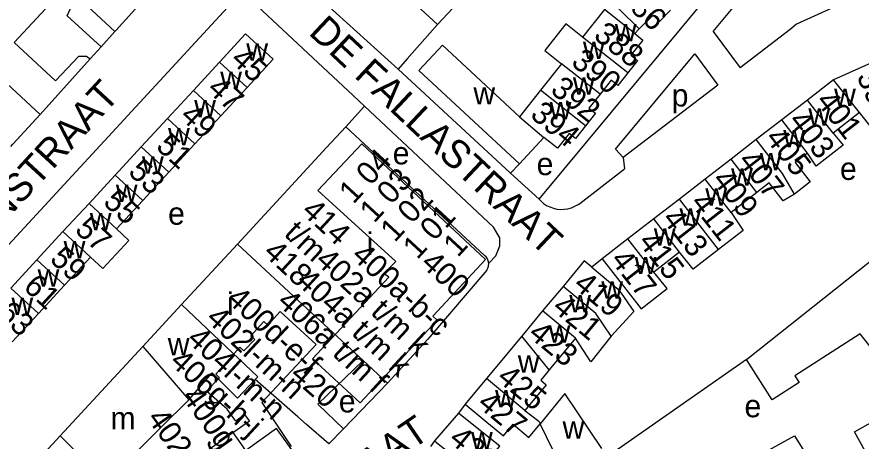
# Model space of a CAD drawing. Extents: x 159045 to 160918, y 380454 to 382516.
# Drawn here: x 159786.4 to 159936.2, y 381507.9 to 381583.2 of the extents above; entities that cross this region are included whole.
import ezdxf

# ---------------------------------------------------------------- set-up
doc = ezdxf.new("R2010")
doc.units = 0
for name, color, linetype in [('BLT_Basislijn', 7, 'Continuous'), ('BLT_Bebouwing', 7, 'Continuous'), ('BLT_Centroide', 7, 'Continuous'), ('BLT_Huisnummer', 7, 'Continuous'), ('BLT_Huisnummer_ tussenligend', 7, 'Continuous'), ('BLT_Huisnummer_reeks', 7, 'Continuous'), ('BLT_Huisnummer_zonder_bebouwing', 7, 'Continuous'), ('BLT_Onderverdeling_panden', 7, 'Continuous'), ('BLT_Plantopo', 7, 'Continuous'), ('BLT_Straatnaam', 7, 'Continuous')]:
    doc.layers.add(name, color=color, linetype=linetype)

msp = doc.modelspace()

# ---------------------------------------------------------------- linework, layer by layer
at = {"layer": 'BLT_Basislijn'}
for p, q in [((159904.79, 381629.03), (159861.07, 381581.84)), ((159879.08, 381550.82), (159931.69, 381614.23)), ((159909.99, 381580.6), (159934.12, 381609.7)), ((159803.8, 381580.61), (159778.83, 381603.82)), ((159848.38, 381593.58), (159861.07, 381581.84)), ((159765.35, 381589.16), (159790.52, 381565.9)), ((159804.04, 381580.87), (159803.8, 381580.61)), ((159896.07, 381580.24), (159896.87, 381581.07)), ((159803.8, 381580.61), (159801.33, 381577.88)), ((159909.99, 381580.6), (159914.75, 381574.14)), ((159801.33, 381577.88), (159799.41, 381575.74)), ((159906.7, 381576.64), (159910.79, 381571.1)), ((159799.41, 381575.74), (159790.52, 381565.9)), ((159874.02, 381555.44), (159854.07, 381573.92)), ((159910.79, 381571.1), (159894.03, 381558.25)), ((159848.08, 381567.38), (159844.75, 381563.69)), ((159894.03, 381558.25), (159894.27, 381556.2)), ((159874.02, 381555.44), (159875.58, 381557.1)), ((159879.08, 381550.82), (159874.02, 381555.44)), ((159886.29, 381550.1), (159894.27, 381556.2)), ((159879.87, 381550.1), (159879.08, 381550.82)), ((159890.29, 381540.22), (159888.45, 381538.75)), ((159915.87, 381522.39), (159891.17, 381505.09)), ((159844.35, 381510.07), (159852.18, 381518.17)), ((159865.97, 381514.42), (159864.79, 381512.84)), ((159794.09, 381508.82), (159785.95, 381500.02)), ((159860.52, 381507.91), (159859.82, 381506.88))]:
    msp.add_line(p, q, dxfattribs=at)
for points in [[(159839.03, 381602.45), (159835.58, 381598.61), (159834.37, 381596.71), (159834.17, 381595.42), (159834.51, 381592.37), (159839.38, 381587.26), (159854.07, 381573.92)], [(159812.23, 381595.28), (159814.81, 381592.83), (159804.04, 381580.87)], [(159941.77, 381589.71), (159924.75, 381581.94), (159923.64, 381580.95), (159914.75, 381574.14)], [(159801.33, 381577.88), (159795.33, 381583.42), (159796.15, 381585.26), (159793.91, 381587.33), (159785.89, 381578.65), (159793.25, 381571.84), (159797.38, 381576.25), (159798.77, 381576.27), (159799.41, 381575.74)], [(159848.08, 381567.38), (159846.1, 381569.24), (159828.23, 381585.97), (159825.45, 381586.12), (159823.76, 381584.89), (159762.94, 381518.98), (159762.66, 381518.45)], [(159861.07, 381581.84), (159859.71, 381580.34), (159855.66, 381575.77), (159854.07, 381573.92)], [(159894.03, 381558.25), (159892.67, 381559.73), (159906.7, 381576.64)], [(159870.14, 381539.48), (159871.41, 381540.76), (159872.09, 381542.53), (159872.09, 381543.96), (159871, 381545.87), (159848.08, 381567.38)], [(159785.32, 381560.2), (159785.67, 381560.59), (159790.52, 381565.9)], [(159879.87, 381550.1), (159880.42, 381549.74), (159881, 381549.45), (159881.62, 381549.23), (159882.26, 381549.09), (159882.91, 381549.03), (159883.56, 381549.05), (159884.21, 381549.15), (159884.84, 381549.32), (159885.44, 381549.58), (159886.01, 381549.9), (159886.29, 381550.1)]]:
    msp.add_lwpolyline(points, dxfattribs=at)
at = {"layer": 'BLT_Bebouwing'}
for p, q in [((159896.07, 381580.24), (159897.5, 381579.11)), ((159817.73, 381570.16), (159822.37, 381575.17)), ((159883.07, 381574.89), (159879.33, 381570.18)), ((159939.15, 381575.53), (159931.35, 381572.05)), ((159827.24, 381570.68), (159822.61, 381565.66)), ((159813.1, 381565.14), (159817.73, 381570.16)), ((159879.33, 381570.18), (159875.6, 381565.47)), ((159926.7, 381568.44), (159922.16, 381564.93)), ((159935.97, 381566.21), (159931.26, 381562.56)), ((159808.46, 381560.13), (159813.1, 381565.14)), ((159822.61, 381565.66), (159817.98, 381560.64)), ((159922.16, 381564.93), (159917.63, 381561.41)), ((159844.75, 381563.69), (159869.4, 381540.86)), ((159879.95, 381561.8), (159875.58, 381557.1)), ((159882.33, 381559.91), (159879.95, 381561.8)), ((159917.63, 381561.41), (159913.16, 381557.95)), ((159803.83, 381555.11), (159808.46, 381560.13)), ((159817.98, 381560.64), (159813.35, 381555.62)), ((159913.16, 381557.95), (159908.59, 381554.41)), ((159813.35, 381555.62), (159808.72, 381550.6)), ((159799.2, 381550.1), (159803.83, 381555.11)), ((159908.59, 381554.41), (159904.01, 381550.86)), ((159904.01, 381550.86), (159899.44, 381547.32)), ((159917.74, 381552.05), (159913.17, 381548.5)), ((159794.56, 381545.08), (159799.2, 381550.1)), ((159808.72, 381550.6), (159804.09, 381545.58)), ((159899.44, 381547.32), (159894.86, 381543.77)), ((159789.93, 381540.07), (159794.56, 381545.08)), ((159894.86, 381543.77), (159890.29, 381540.22)), ((159825.53, 381542.87), (159815.62, 381532.14)), ((159799.46, 381540.56), (159794.83, 381535.55)), ((159904.03, 381541.4), (159899.46, 381537.85)), ((159915.87, 381522.39), (159940.17, 381541.66)), ((159785.29, 381535.05), (159789.93, 381540.07)), ((159794.83, 381535.55), (159790.2, 381530.53)), ((159883.34, 381535.35), (159879.71, 381530.98)), ((159815.62, 381532.14), (159808.75, 381524.7)), ((159790.2, 381530.53), (159785.57, 381525.51)), ((159879.71, 381530.98), (159876.01, 381526.51)), ((159876.01, 381526.51), (159869.75, 381518.97)), ((159885.54, 381526.14), (159880.87, 381520.5)), ((159808.75, 381524.7), (159804.29, 381519.88)), ((159847.84, 381522.19), (159839.82, 381514.42)), ((159852.18, 381518.17), (159847.84, 381522.19)), ((159804.29, 381519.88), (159794.09, 381508.82)), ((159816.89, 381515.22), (159821.04, 381519.99)), ((159836.25, 381512.18), (159828.69, 381518.81)), ((159869.75, 381518.97), (159865.97, 381514.42)), ((159880.32, 381517.89), (159876.55, 381513.33)), ((159883.66, 381516.34), (159879.27, 381510.91)), ((159890.2, 381506.54), (159883.66, 381516.34)), ((159844.35, 381510.07), (159839.82, 381514.42)), ((159864.79, 381512.84), (159860.52, 381507.91)), ((159841.74, 381507.36), (159844.35, 381510.07))]:
    msp.add_line(p, q, dxfattribs=at)
for points in [[(159895.05, 381591.65), (159890.66, 381587.17), (159893.31, 381584.57), (159896.87, 381581.07)], [(159896.07, 381580.24), (159893.58, 381582.21), (159890.68, 381584.51), (159886.8, 381579.6)], [(159902.43, 381584.4), (159900.47, 381582.41), (159899.31, 381583.55), (159896.87, 381581.07)], [(159886.8, 381579.6), (159883.82, 381581.96), (159880.09, 381577.25), (159883.07, 381574.89)], [(159822.37, 381575.17), (159826.99, 381580.18), (159831.86, 381575.69), (159827.24, 381570.68)], [(159875.58, 381557.1), (159857.74, 381573.7), (159861.15, 381577.36), (159861.92, 381578.19), (159875.6, 381565.47)], [(159897.5, 381579.11), (159895.38, 381576.43), (159896.57, 381575.49), (159894.81, 381573.26)], [(159894.81, 381573.26), (159893.05, 381571.04), (159891.88, 381571.96), (159889.91, 381569.48)], [(159931.35, 381572.05), (159926.7, 381568.44)], [(159889.91, 381569.48), (159887.94, 381566.99), (159889.08, 381566.09), (159887.32, 381563.86)], [(159944.02, 381565.92), (159938.24, 381563.33), (159935.97, 381566.21)], [(159844.75, 381563.69), (159841.36, 381560.01), (159825.53, 381542.87)], [(159887.32, 381563.86), (159885.55, 381561.62), (159884.4, 381562.53), (159882.33, 381559.91)], [(159931.26, 381562.56), (159933.07, 381560.44), (159928.25, 381556.69), (159926.73, 381559.04)], [(159926.73, 381559.04), (159924.54, 381557.34), (159927.22, 381553.89), (159924.41, 381551.7)], [(159924.41, 381551.7), (159922.4, 381550.55), (159919.91, 381553.74), (159917.74, 381552.05)], [(159913.17, 381548.5), (159915.28, 381545.27), (159910.94, 381541.9)], [(159804.09, 381545.58), (159806.28, 381543.52), (159801.66, 381538.51), (159799.46, 381540.56)], [(159910.94, 381541.9), (159906.43, 381538.39), (159904.03, 381541.4)], [(159870.14, 381539.48), (159870.07, 381539.87), (159869.91, 381540.24), (159869.69, 381540.58), (159869.4, 381540.86)], [(159890.29, 381540.22), (159897.18, 381531.35), (159901.83, 381534.96), (159899.46, 381537.85)], [(159869.83, 381538.21), (159870.01, 381538.57), (159870.12, 381538.95), (159870.14, 381539.48)], [(159888.45, 381538.75), (159887.09, 381539.87), (159883.34, 381535.35)], [(159888.45, 381538.75), (159892.91, 381535.05), (159893.63, 381534.13), (159895.89, 381530.86), (159891.89, 381526.49)], [(159869.83, 381538.21), (159859.32, 381526), (159852.18, 381518.17)], [(159937.83, 381524.66), (159936.09, 381526.91), (159924.45, 381519.49), (159925.24, 381518.25), (159920.47, 381515.21), (159915.87, 381522.39)], [(159891.89, 381526.49), (159888.27, 381521.93), (159885.54, 381526.14)], [(159828.69, 381518.81), (159825.53, 381515.52), (159821.04, 381519.99)], [(159880.87, 381520.5), (159879.37, 381518.68), (159880.32, 381517.89)], [(159811.92, 381510.27), (159816.89, 381515.22)], [(159865.97, 381514.42), (159869.82, 381511.23), (159872.77, 381508.78), (159874.51, 381510.88), (159877.28, 381508.51), (159879.27, 381510.91)], [(159876.55, 381513.33), (159879.03, 381511.39), (159879.27, 381510.91)], [(159841.74, 381507.36), (159837.78, 381510.83), (159836.25, 381512.18)], [(159860.52, 381507.91), (159864.42, 381504.78), (159867.11, 381502.62), (159866.97, 381502.45), (159869.86, 381500), (159871.91, 381502.3), (159869.71, 381504.2), (159872.09, 381506.95), (159868.68, 381509.7), (159864.79, 381512.84)], [(159794.09, 381508.82), (159802.26, 381500.66), (159811.92, 381510.28)], [(159884.22, 381501.89), (159882.63, 381503.99), (159879.27, 381510.91)], [(159937.71, 381497.42), (159933.89, 381504.38), (159936.95, 381506.06), (159935.05, 381509.52), (159938.45, 381511.39)], [(159837.07, 381503.66), (159834.17, 381507.73), (159832.5, 381510.08), (159827.04, 381506.2), (159824.65, 381509.57), (159822.2, 381507.82)], [(159919.94, 381506.34), (159924.4, 381508.81), (159928.52, 381502.22), (159928.69, 381502.27), (159929.95, 381500), (159932.38, 381495.64)]]:
    msp.add_lwpolyline(points, dxfattribs=at)
at = {"layer": 'BLT_Onderverdeling_panden'}
for p, q in [((159894.81, 381573.26), (159886.8, 381579.6)), ((159827.24, 381570.68), (159822.37, 381575.17)), ((159889.91, 381569.48), (159883.07, 381574.89)), ((159935.97, 381566.21), (159931.35, 381572.05)), ((159822.61, 381565.66), (159817.73, 381570.16)), ((159887.32, 381563.86), (159879.33, 381570.18)), ((159931.26, 381562.56), (159926.7, 381568.44)), ((159817.98, 381560.64), (159813.1, 381565.14)), ((159875.6, 381565.47), (159879.95, 381561.8)), ((159926.73, 381559.04), (159922.16, 381564.93)), ((159813.35, 381555.62), (159808.46, 381560.13)), ((159917.74, 381552.05), (159913.16, 381557.95)), ((159808.72, 381550.6), (159803.83, 381555.11)), ((159913.17, 381548.5), (159908.59, 381554.41)), ((159910.94, 381541.9), (159904.01, 381550.86)), ((159804.09, 381545.58), (159799.2, 381550.1)), ((159904.03, 381541.4), (159899.44, 381547.32)), ((159799.46, 381540.56), (159794.56, 381545.08)), ((159899.46, 381537.85), (159894.86, 381543.77)), ((159836.34, 381532.85), (159825.53, 381542.87)), ((159794.83, 381535.55), (159789.93, 381540.07)), ((159790.2, 381530.53), (159785.29, 381535.05)), ((159847.84, 381522.19), (159836.34, 381532.85)), ((159885.54, 381526.14), (159879.71, 381530.98)), ((159880.87, 381520.5), (159876.01, 381526.51)), ((159808.75, 381524.7), (159816.89, 381515.22)), ((159876.55, 381513.33), (159869.75, 381518.97))]:
    msp.add_line(p, q, dxfattribs=at)
for points in [[(159924.41, 381551.7), (159922.3, 381555.39), (159917.63, 381561.41)], [(159891.89, 381526.49), (159889.16, 381530.52), (159883.34, 381535.35)], [(159815.62, 381532.14), (159829.16, 381519.29), (159828.69, 381518.81)]]:
    msp.add_lwpolyline(points, dxfattribs=at)
at = {"layer": 'BLT_Plantopo'}
msp.add_lwpolyline([(159839.82, 381552.36), (159847.61, 381560.66), (159869.59, 381540.15), (159860.21, 381530.07), (159860.98, 381529.35), (159847.32, 381514.65), (159838.89, 381522.49), (159852.39, 381536.99), (159851.55, 381537.64), (159853.64, 381539.78)], close=True, dxfattribs=at)
msp.add_lwpolyline([(159811.61, 381500.16), (159827.68, 381511.47), (159826.88, 381512.58), (159825.24, 381511.41), (159823.73, 381513.52), (159820.04, 381516.72), (159822.36, 381519.1), (159821.7, 381519.73), (159825.99, 381524.55), (159826.66, 381523.93), (159828.6, 381525.91), (159827.89, 381526.59), (159830.25, 381529.09), (159830.94, 381528.46), (159833.12, 381530.89), (159839.53, 381525.01), (159829.89, 381514.71), (159835.06, 381506.91)], dxfattribs=at)

# ---------------------------------------------------------------- texts
at = {"layer": 'BLT_Centroide'}
for s, p in [('w', (159892.52, 381578.88)), ('w', (159827.11, 381575.42)), ('w', (159886.87, 381575.72)), ('w', (159822.48, 381570.42)), ('w', (159885.09, 381569.38)), ('w', (159867.42, 381567.66)), ('p', (159902.62, 381567.3)), ('w', (159931.45, 381567.41)), ('w', (159817.86, 381565.39)), ('w', (159880.96, 381565.03)), ('w', (159926.89, 381563.88)), ('w', (159813.22, 381560.39)), ('w', (159922.42, 381560.03)), ('e', (159853.1, 381557.02)), ('w', (159808.59, 381555.36)), ('e', (159878.65, 381555.11)), ('w', (159918.27, 381555.97)), ('e', (159932.49, 381554.26)), ('w', (159913.17, 381553.22)), ('w', (159803.95, 381550.36)), ('w', (159908.59, 381549.69)), ('e', (159813.23, 381546.3)), ('w', (159799.33, 381545.33)), ('w', (159904.02, 381546.12)), ('i', (159848.48, 381540.94)), ('w', (159899.45, 381542.59)), ('w', (159794.69, 381540.31)), ('w', (159896.06, 381537.52)), ('w', (159790.06, 381535.3)), ('w', (159890.12, 381533.19)), ('i', (159823.69, 381530.27)), ('w', (159785.42, 381530.28)), ('w', (159884.44, 381530.75)), ('w', (159880.78, 381525.36)), ('w', (159813.17, 381523.09)), ('w', (159875.31, 381520.02)), ('w', (159871.26, 381513.88)), ('e', (159843.53, 381512.96)), ('e', (159915.54, 381512.1)), ('m', (159803, 381509.94)), ('w', (159883.25, 381508.28)), ('w', (159867, 381506.41))]:
    msp.add_text(s, height=4, dxfattribs=at).set_placement(p)
at = {"layer": 'BLT_Huisnummer'}
for s, rotation, p in [('388', 321.6345, (159888.56, 381579.55)), ('45', 317.3116, (159824.13, 381575.36)), ('399', 294.083, (159935.39, 381572.66)), ('401', 307.8474, (159928.08, 381568.2)), ('394', 319.7956, (159877.31, 381565.55)), ('49', 317.3077, (159815.15, 381565.34)), ('405', 307.8474, (159919.07, 381561.65)), ('53', 317.3096, (159805.96, 381555.45)), ('409', 307.8427, (159909.66, 381554.24)), ('57', 317.3115, (159796.49, 381545.17)), ('413', 307.8387, (159900.76, 381547.29)), ('417', 307.8401, (159891.61, 381540.01)), ('61', 317.3076, (159787.34, 381535.01)), ('419', 320.4106, (159884.97, 381535.29)), ('423', 320.3143, (159876.95, 381526.56)), ('420', 318.7486, (159834.66, 381519.35)), ('427', 320.3147, (159867.92, 381514.16)), ('429', 320.3147, (159862.86, 381507.86))]:
    msp.add_text(s, height=4, rotation=rotation, dxfattribs=at).set_placement(p)
at = {"layer": 'BLT_Huisnummer_ tussenligend'}
for s, rotation, p in [('386', 315.521, (159892.92, 381586.73)), ('390', 321.6345, (159884.57, 381574.8)), ('47', 317.3116, (159819.98, 381570.15)), ('392', 321.6345, (159880.9, 381569.88)), ('403', 307.8474, (159923.21, 381564.72)), ('51', 317.3077, (159810.89, 381559.96)), ('407', 307.8427, (159914.26, 381557.62)), ('55', 317.3096, (159801.52, 381550.08)), ('411', 307.8387, (159905.79, 381550.15)), ('415', 307.8401, (159896.53, 381543.22)), ('59', 317.3115, (159792.05, 381539.95)), ('421', 320.4106, (159881.21, 381531.22)), ('63', 317.3076, (159782.71, 381530.25)), ('425', 320.3143, (159871.39, 381518.76))]:
    msp.add_text(s, height=4, rotation=rotation, dxfattribs=at).set_placement(p)
at = {"layer": 'BLT_Huisnummer_reeks'}
for s, rotation, p in [('414', 317.1687, (159836.72, 381548.43)), ('t/m', 317.1687, (159833.62, 381544.49)), ('1', 47.2787, (159864.65, 381540.37)), ('418', 317.1687, (159829.93, 381541.09))]:
    msp.add_text(s, height=4, rotation=rotation, dxfattribs=at).set_placement(p)
at = {"layer": 'BLT_Huisnummer_zonder_bebouwing'}
for s, rotation, p in [('1 04', 47.2787, (159846.12, 381549.82)), ('1 03', 47.2787, (159849.8, 381546.44)), ('1 02', 47.2787, (159853.47, 381543.04)), ('1 01', 47.2787, (159857.46, 381539.98)), ('400a-b-c', 317.2787, (159845.58, 381540.52)), ('402a t/m k', 317.2787, (159839.16, 381539.65)), ('400', 317.2787, (159857.88, 381539.16)), ('404a t/m k', 317.2787, (159835.77, 381535.98)), ('400d-e-f', 317.2787, (159823.37, 381532.84)), ('406a t/m f', 317.2787, (159832.37, 381532.31)), ('402l-m-n', 317.2787, (159819.75, 381529.37)), ('404l-m-n', 317.2787, (159816.36, 381525.7)), ('406g-h-j', 317.2787, (159813.32, 381521.7)), ('400g t/m n', 305.2787, (159815.53, 381515.73)), ('402p t/m w', 305.2787, (159809.37, 381511.91))]:
    msp.add_text(s, height=4, rotation=rotation, dxfattribs=at).set_placement(p)
at = {"layer": 'BLT_Straatnaam'}
for s, rotation, p in [('DE FALLASTRAAT', 316.7776, (159837.99, 381580.25)), ('SCHUMANNSTRAAT', 47.2729, (159760.73, 381521.29)), ('LAAGSTRAAT', 34.4504, (159823.47, 381483.58))]:
    msp.add_text(s, height=5, rotation=rotation, dxfattribs=at).set_placement(p)

doc.saveas('drawing.dxf')
